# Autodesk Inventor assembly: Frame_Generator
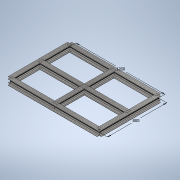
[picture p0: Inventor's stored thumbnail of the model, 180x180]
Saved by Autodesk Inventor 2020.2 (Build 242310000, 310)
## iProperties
Created: 2020-01
Part Number: Frame_Generator
Document SubType Name: Assembly
Designer: thira
_SolveAssemblyDoc: Frame Generator Solve Assembly
_Version: 15.0.0
Author: thira
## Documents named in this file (3)
- F:\99.โปรแกรมอัดหน้าจอ\Synergysoft\FRAME\Frame_Generator.iam
- F:\99.โปรแกรมอัดหน้าจอ\Synergysoft\FRAME\Structure.ipt
- F:\99.โปรแกรมอัดหน้าจอ\Synergysoft\FRAME\Frame_Generator\Frame\Frame 1580185766013.iam
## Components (2 placed, 2 different names)
1. Structure:1
2. Frame 1580185766013:1 [sub-assembly]
